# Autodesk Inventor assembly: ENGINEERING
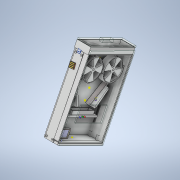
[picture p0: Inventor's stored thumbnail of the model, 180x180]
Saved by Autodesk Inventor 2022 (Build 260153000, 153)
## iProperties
Created: 2021-06
Part Number: ENGINEERING
Document SubType Name: Assembly
Designer: Dell
Author: Dell
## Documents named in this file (19)
- C:\Users\USER\Desktop\pp\ENGINEERING (22) (1) (1).iam
- C:\Users\USER\Desktop\pp\casing (1).ipt
- C:\Users\USER\Desktop\pp\key.ipt
- C:\Users\USER\Desktop\pp\led light.ipt
- C:\Users\USER\Desktop\pp\transfer pipe (1).ipt
- C:\Users\USER\Desktop\pp\IR SENSOR.ipt
- C:\Users\USER\Desktop\pp\stepper motor of 20 by 20 mm.ipt
- C:\Users\USER\Desktop\pp\Part1 (1).ipt
- C:\Users\USER\Desktop\pp\Part2 (1).ipt
- C:\Users\USER\Desktop\pp\lcd screen.ipt
- C:\Users\USER\Desktop\pp\circular pill box.ipt
- C:\Users\USER\Desktop\pp\Arduino_Uno.ipt
- C:\Users\USER\Desktop\pp\buzzer (1) (1).ipt
- C:\Users\USER\Desktop\pp\clamp (2) (1).ipt
- C:\Users\USER\Desktop\pp\Nut.ipt
- C:\Users\USER\Desktop\pp\red led.ipt
- C:\Users\USER\Desktop\pp\green led.ipt
- C:\Users\USER\Desktop\pp\revised new glass material.ipt
- C:\Users\USER\Desktop\pp\opener.ipt
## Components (26 placed, 18 different names)
1. casing (1):1 — Mate:3, Mate:5, Mate:6, Mate:8, Flush:1, Flush:2, Flush:3, Flush:4, Flush:5, Mate:11, Mate:13, Mate:14, Mate:15, Mate:16, Mate:17, Mate:18, Mate:19, Mate:21, Mate:22, Mate:23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
2. key:1 — Mate:13
3. led light:1 — Mate:29
4. led light:2 — Mate:26
5. IR SENSOR:1 — Mate:25
6. IR SENSOR:2 — Mate:24
7. stepper motor of 20 by 20 mm:3 — Mate:6, Mate:7, Mate:8, Flush:1
8. stepper motor of 20 by 20 mm:4 — Mate:3, Mate:4, Mate:5, Flush:4
9. Part1 (1):1 — Mate:7, Flush:2, Mate:10
10. Part1 (1):2 — Mate:4, Flush:3, Mate:9
11. Part2 (1):1 — Mate:9, Flush:5
12. Part2 (1):2 — Mate:10, Mate:11
13. transfer pipe (1):3 — Mate:16
14. transfer pipe (1):4 — Mate:18
15. lcd screen:1
16. circular pill box:1 — Mate:14
17. circular pill box:2 — Mate:15
18. Arduino_Uno:1 — Mate:17
19. buzzer (1) (1):1 — Mate:19
20. clamp (2) (1):1 — Mate:21
21. clamp (2) (1):2 — Mate:22
22. Nut:1 — Mate:23
23. red led:1 — Mate:28
24. green led:1 — Mate:27
25. revised new glass material:1 — Mate:30, Flush:6
26. opener:1 — Mate:31
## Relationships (33: Mate 27, Flush 6)
- Mate:3: casing (1):1 ↔ stepper motor of 20 by 20 mm:4
- Mate:4: stepper motor of 20 by 20 mm:4 ↔ Part1 (1):2
- Mate:5: casing (1):1 ↔ stepper motor of 20 by 20 mm:4
- Mate:6: casing (1):1 ↔ stepper motor of 20 by 20 mm:3
- Mate:7: stepper motor of 20 by 20 mm:3 ↔ Part1 (1):1
- Mate:8: casing (1):1 ↔ stepper motor of 20 by 20 mm:3
- Flush:1: casing (1):1 ↔ stepper motor of 20 by 20 mm:3
- Flush:2: casing (1):1 ↔ Part1 (1):1
- Flush:3: casing (1):1 ↔ Part1 (1):2
- Flush:4: casing (1):1 ↔ stepper motor of 20 by 20 mm:4
- Mate:9: Part1 (1):2 ↔ Part2 (1):1
- Flush:5: casing (1):1 ↔ Part2 (1):1
- Mate:10: Part1 (1):1 ↔ Part2 (1):2
- Mate:11: casing (1):1 ↔ Part2 (1):2
- Mate:13: casing (1):1 ↔ key:1
- Mate:14: casing (1):1 ↔ circular pill box:1
- Mate:15: casing (1):1 ↔ circular pill box:2
- Mate:16: casing (1):1 ↔ transfer pipe (1):3
- Mate:17: casing (1):1 ↔ Arduino_Uno:1
- Mate:18: casing (1):1 ↔ transfer pipe (1):4
- Mate:19: casing (1):1 ↔ buzzer (1) (1):1
- Mate:21: casing (1):1 ↔ clamp (2) (1):1
- Mate:22: casing (1):1 ↔ clamp (2) (1):2
- Mate:23: casing (1):1 ↔ Nut:1
- Mate:24: casing (1):1 ↔ IR SENSOR:2
- Mate:25: casing (1):1 ↔ IR SENSOR:1
- Mate:26: casing (1):1 ↔ led light:2
- Mate:27: casing (1):1 ↔ green led:1
- Mate:28: casing (1):1 ↔ red led:1
- Mate:29: casing (1):1 ↔ led light:1
- Mate:30: casing (1):1 ↔ revised new glass material:1
- Flush:6: casing (1):1 ↔ revised new glass material:1
- Mate:31: casing (1):1 ↔ opener:1
